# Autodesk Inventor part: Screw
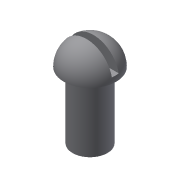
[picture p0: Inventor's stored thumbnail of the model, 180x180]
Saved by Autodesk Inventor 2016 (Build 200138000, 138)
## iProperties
Created: 2009-04
Part Number: Screw
Document SubType Name: Modeling
Designer: Sham
Density: 1 g/cm^3
Material: Generic
Appearance: Default
Author: Sham
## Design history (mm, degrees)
sketch "Sketch1"
  geometry: C1 r 10 at (0, 0)
  constraints: 1 centre point
  dimensions: "d0" = 20 diameter of C1
extrude "Extrusion1" new body sketch "Sketch1" distance "d1" = 38; taper "d2" = 0 deg
sketch "Sketch2"
  geometry: L1 (0, 38)-(-15, 38); L2 (-10, 38)-(10, 38) reference; L3 (0, 38)-(0, 53); A1 r 15 centre (0, 38) between (0, 53) and (-15, 38)
  constraints: 4 end point, 2 point on circle, 1 centre point, 1 collinear, 1 perpendicular
  dimensions: "d3" = 15 radius of A1
revolve "Revolution1" sketch "Sketch2" stored, may be unused: angle "d4" = 90 deg
sketch "Sketch3"
  geometry: L1 (2, 54)-(2, 41); L2 (2, 41)-(-2, 41); L3 (-2, 41)-(-2, 54); L4 (-2, 54)-(2, 54); L5 (15, 38)-(-15, 38) reference
  constraints: 8 end point, 2 parallel, 1 perpendicular, 1 vertical
  dimensions: "d5" = 3 distance between parallel lines of L5 L2; "d6" = 4 distance between parallel lines of L3 L1
extrude "Extrusion2" cut sketch "Sketch3" stored distance "d7" = 38; taper "d8" = 0 deg
body "Solid1"
